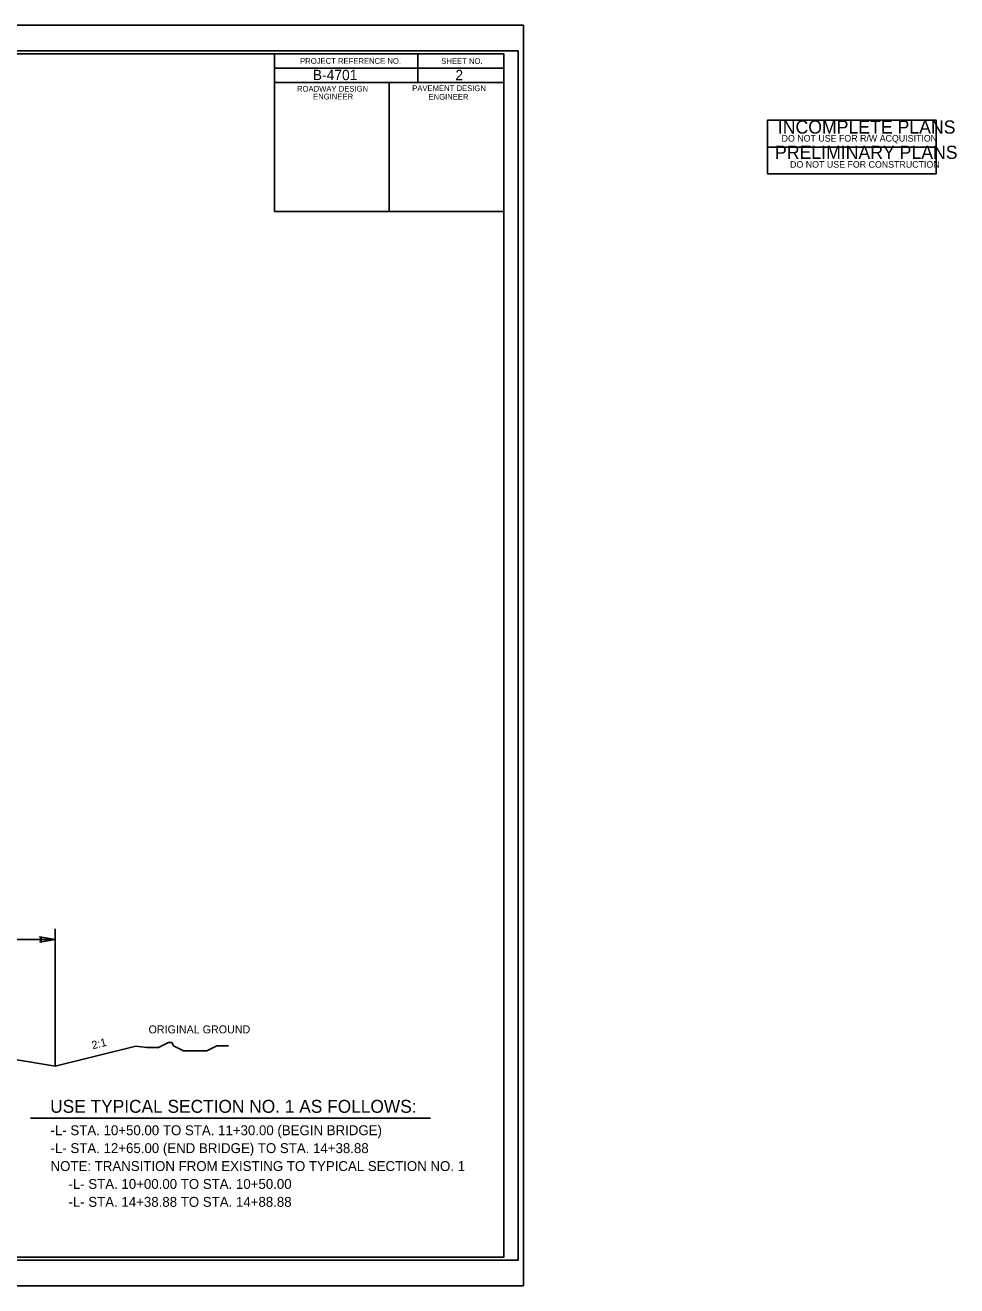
# Model space of a CAD drawing. Extents: x 106738.7 to 106779.9, y 105993.5 to 106034.9.
# Drawn here: x 106763.66 to 106779.92, y 106012.88 to 106034.88 of the extents above; entities that cross this region are included whole.
import ezdxf

# ---------------------------------------------------------------- set-up
doc = ezdxf.new("R2010")
doc.units = 0
for name, color, linetype in [('Old_Level_1', 7, 'Continuous'), ('Old_Level_11', 7, 'Continuous'), ('Sheet Cutting Line CELL', 7, 'Continuous'), ('Sheet Plot Border Inside CELL', 7, 'Continuous'), ('Sheet Plot Border Outside CELL', 7, 'Continuous'), ('Sheet Sticker Incomplete CELL', 7, 'Continuous'), ('Sheet Sticker Preliminary CELL', 7, 'Continuous'), ('Sheet Typical CELL', 7, 'Continuous'), ('Typical Hinge Slope Arterial CELL', 7, 'Continuous')]:
    doc.layers.add(name, color=color, linetype=linetype)

msp = doc.modelspace()

# ---------------------------------------------------------------- linework, layer by layer
at = {"layer": 'Old_Level_1'}
msp.add_line((106763.756, 106015.808), (106770.733, 106015.808), dxfattribs=at)
at = {"layer": 'Old_Level_11'}
for p, q in [((106764.183, 106016.714), (106764.183, 106019.112)), ((106760.217, 106018.924), (106764.183, 106018.924))]:
    msp.add_line(p, q, dxfattribs=at)
msp.add_lwpolyline([(106763.919, 106018.879), (106764.183, 106018.924), (106763.917, 106018.971), (106763.951, 106018.924)], close=True, dxfattribs=at)
at = {"layer": 'Sheet Cutting Line CELL'}
for p, q in [((106772.356, 106034.882), (106738.676, 106034.882)), ((106738.676, 106012.882), (106772.356, 106012.882))]:
    msp.add_line(p, q, dxfattribs=at)
at = {"layer": 'Sheet Plot Border Inside CELL'}
msp.add_lwpolyline([(106772.266, 106034.433), (106738.936, 106034.433), (106738.936, 106013.331), (106772.266, 106013.331)], close=True, dxfattribs=at)
at = {"layer": 'Sheet Plot Border Outside CELL'}
msp.add_lwpolyline([(106772.356, 106034.882), (106738.676, 106034.882), (106738.676, 106012.882), (106772.356, 106012.882)], close=True, dxfattribs=at)
at = {"layer": 'Sheet Sticker Incomplete CELL'}
msp.add_lwpolyline([(106776.616, 106032.756), (106776.616, 106033.226), (106779.556, 106033.226), (106779.556, 106032.756)], close=True, dxfattribs=at)
at = {"layer": 'Sheet Sticker Preliminary CELL'}
msp.add_lwpolyline([(106776.616, 106032.286), (106776.616, 106032.756), (106779.556, 106032.756), (106779.556, 106032.286)], close=True, dxfattribs=at)
at = {"layer": 'Sheet Typical CELL'}
for p, q in [((106770.516, 106034.381), (106770.516, 106033.881)), ((106768.015, 106034.131), (106772.016, 106034.131)), ((106770.016, 106033.881), (106770.016, 106031.632))]:
    msp.add_line(p, q, dxfattribs=at)
for points in [[(106772.016, 106034.382), (106742.016, 106034.382), (106742.016, 106013.382), (106772.016, 106013.382)], [(106768.015, 106034.382), (106772.016, 106034.382), (106772.016, 106033.881), (106768.015, 106033.881)], [(106768.015, 106033.881), (106770.016, 106033.881), (106770.016, 106031.631), (106768.015, 106031.631)], [(106770.016, 106033.881), (106772.016, 106033.881), (106772.016, 106031.631), (106770.016, 106031.631)]]:
    msp.add_lwpolyline(points, close=True, dxfattribs=at)
at = {"layer": 'Typical Hinge Slope Arterial CELL'}
for p, q in [((106764.183, 106016.714), (106761.361, 106017.184)), ((106765.594, 106017.066), (106764.183, 106016.714))]:
    msp.add_line(p, q, dxfattribs=at)
msp.add_lwpolyline([(106765.594, 106017.066), (106765.787, 106017.042), (106765.845, 106017.042), (106765.932, 106017.042), (106765.99, 106017.042), (106766.048, 106017.071), (106766.106, 106017.1), (106766.164, 106017.129), (106766.222, 106017.129), (106766.251, 106017.071), (106766.309, 106017.042), (106766.367, 106017.013), (106766.425, 106016.984), (106766.483, 106016.984), (106766.541, 106016.984), (106766.598, 106016.984), (106766.656, 106016.984), (106766.714, 106016.984), (106766.772, 106016.984), (106766.83, 106016.984), (106766.888, 106017.013), (106766.946, 106017.042), (106767.004, 106017.071), (106767.091, 106017.071), (106767.149, 106017.071), (106767.207, 106017.071)], dxfattribs=at)

# ---------------------------------------------------------------- texts
at = {"layer": 'Old_Level_1'}
for s, p in [('-L- STA. 10+50.00 TO STA. 11+30.00 (BEGIN BRIDGE)', (106764.105, 106015.51)), ('-L- STA. 12+65.00 (END BRIDGE) TO STA. 14+38.88', (106764.105, 106015.198))]:
    msp.add_text(s, height=0.17289, rotation=360, dxfattribs=at).set_placement(p)
at = {"layer": 'Old_Level_11'}
for s, height, p in [('B-4701', 0.1806, (106768.68, 106033.924)), ('2', 0.181, (106771.169, 106033.922)), ('USE TYPICAL SECTION NO. 1 AS FOLLOWS:', 0.22578, (106764.099, 106015.901)), ('NOTE: TRANSITION FROM EXISTING TO TYPICAL SECTION NO. 1', 0.17289, (106764.105, 106014.885)), ('-L- STA. 10+00.00 TO STA. 10+50.00', 0.17289, (106764.417, 106014.573)), ('-L- STA. 14+38.88 TO STA. 14+88.88', 0.17289, (106764.417, 106014.26))]:
    msp.add_text(s, height=height, rotation=360, dxfattribs=at).set_placement(p)
at = {"layer": 'Sheet Sticker Incomplete CELL'}
for s, height, p in [('INCOMPLETE PLANS', 0.2304, (106776.795, 106032.99)), ('DO NOT USE FOR R/W ACQUISITION', 0.1152, (106776.86, 106032.851))]:
    msp.add_text(s, height=height, dxfattribs=at).set_placement(p)
at = {"layer": 'Sheet Sticker Preliminary CELL'}
for s, height, p in [('PRELIMINARY PLANS', 0.2304, (106776.746, 106032.549)), ('DO NOT USE FOR CONSTRUCTION', 0.1152, (106777.008, 106032.395)), ('DO NOT USE FOR CONSTRUCTION', 0.1152, (106777.008, 106032.395))]:
    msp.add_text(s, height=height, dxfattribs=at).set_placement(p)
at = {"layer": 'Sheet Typical CELL'}
for s, p in [('PROJECT REFERENCE NO.', (106768.459, 106034.208)), ('SHEET NO.', (106770.922, 106034.206)), ('ROADWAY DESIGN', (106768.405, 106033.723)), ('ENGINEER', (106768.686, 106033.586)), ('PAVEMENT DESIGN', (106770.415, 106033.732)), ('ENGINEER', (106770.699, 106033.583))]:
    msp.add_text(s, height=0.1, dxfattribs=at).set_placement(p)
at = {"layer": 'Typical Hinge Slope Arterial CELL'}
msp.add_text('ORIGINAL GROUND', height=0.13962, dxfattribs=at).set_placement((106765.815, 106017.287))
msp.add_text('2:1', height=0.1396, rotation=14.0362, dxfattribs=at).set_placement((106764.842, 106017.009))

doc.saveas('drawing.dxf')
